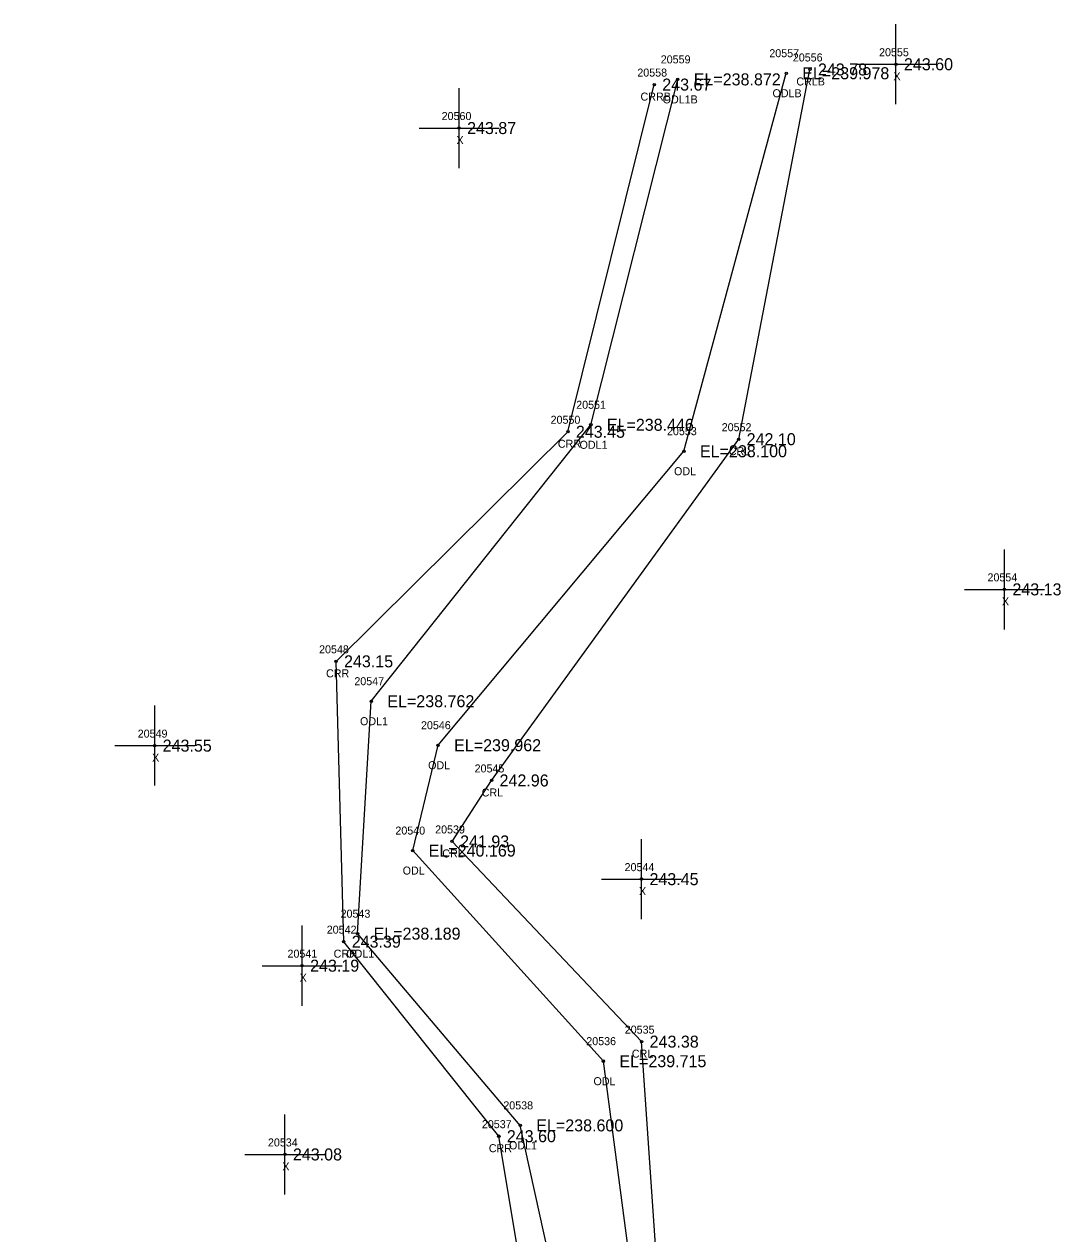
# Model space of a CAD drawing. Extents: x 2275563 to 2277161, y 1075719 to 1076412.
# Drawn here: x 2276399.9 to 2276529.5, y 1076261.3 to 1076412.4 of the extents above; entities that cross this region are included whole.
import ezdxf

# ---------------------------------------------------------------- set-up
doc = ezdxf.new("R2010")
doc.units = 0
for name, color, linetype in [('RD_EX_H2O', 7, 'Continuous'), ('RD_EX_H2O_txCode', 7, 'Continuous'), ('RD_EX_Misc', 7, 'Continuous'), ('RD_EX_Misc_txCode', 7, 'Continuous'), ('RD_EX_TX_H2O_ELEV', 7, 'Continuous'), ('RD_EX_TX_Misc_ELEV', 7, 'Continuous'), ('RD_SMD_Locator', 7, 'Continuous')]:
    doc.layers.add(name, color=color, linetype=linetype)

msp = doc.modelspace()

# ---------------------------------------------------------------- linework, layer by layer
at = {"layer": 'RD_EX_H2O'}
for points in [[(2276371.99, 1076084.86), (2276359.12, 1076090.36), (2276349.87, 1076095.47), (2276335.93, 1076128.95), (2276310.08, 1076180.39), (2276310.66, 1076200.13), (2276321.83, 1076198.34), (2276333.62, 1076185.76), (2276354.83, 1076182.14), (2276364.71, 1076198.02), (2276372.09, 1076234.22), (2276380.37, 1076246.34), (2276391.97, 1076247.22), (2276452.13, 1076223.15), (2276471.36, 1076222.63), (2276478.94, 1076232.98), (2276472.33, 1076282.9), (2276448.49, 1076309.21), (2276451.67, 1076322.37), (2276482.4, 1076359.1), (2276495.19, 1076406.32)], [(2276374.66, 1076053.77), (2276377.62, 1076058.48), (2276375.93, 1076085.62), (2276365.46, 1076098.25), (2276358.16, 1076095.88), (2276352.82, 1076100.61), (2276340.06, 1076130.39), (2276314.72, 1076182.94), (2276314.31, 1076195.95), (2276321.34, 1076195.98), (2276333.33, 1076184.02), (2276355.21, 1076176.64), (2276375.26, 1076196.07), (2276380, 1076232.36), (2276383.62, 1076239.24), (2276390.64, 1076244.46), (2276451.84, 1076220.12), (2276472.79, 1076219.91), (2276480.77, 1076232.08), (2276477.11, 1076285.34), (2276453.42, 1076310.35), (2276458.35, 1076317.97), (2276489.24, 1076360.6), (2276498.15, 1076406.79)], [(2276337.52, 1076082.32), (2276338.14, 1076090.91), (2276325.39, 1076121.38), (2276301.23, 1076176.38), (2276301.47, 1076212.03), (2276303.94, 1076212.33), (2276322.96, 1076208.7), (2276333.72, 1076197.42), (2276353.59, 1076194.54), (2276358.22, 1076208.33), (2276360.94, 1076233.4), (2276370.36, 1076250.64), (2276386.18, 1076258.85), (2276454.86, 1076231.51), (2276469.16, 1076242), (2276461.94, 1076274.88), (2276441.6, 1076298.83), (2276443.32, 1076327.87), (2276470.76, 1076362.4), (2276481.62, 1076405.55)], [(2276306.58, 1076220.1), (2276325.39, 1076214.04), (2276335.43, 1076205.2), (2276348.24, 1076201.78), (2276353.6, 1076208.85), (2276358.58, 1076232.7), (2276367.82, 1076252.56), (2276386.4, 1076261.78), (2276453.31, 1076239.6), (2276463.95, 1076245.24), (2276459.26, 1076273.53), (2276439.87, 1076297.83), (2276438.91, 1076332.85), (2276467.89, 1076361.53), (2276478.69, 1076404.9)]]:
    msp.add_lwpolyline(points, dxfattribs=at)
at = {"layer": 'RD_EX_Misc'}
for p, q in [((2276508.9, 1076402.44), (2276508.9, 1076412.44)), ((2276503.9, 1076407.44), (2276513.9, 1076407.44)), ((2276454.29, 1076394.47), (2276454.29, 1076404.47)), ((2276449.29, 1076399.47), (2276459.29, 1076399.47)), ((2276522.46, 1076336.84), (2276522.46, 1076346.84)), ((2276517.46, 1076341.84), (2276527.46, 1076341.84)), ((2276416.24, 1076317.32), (2276416.24, 1076327.32)), ((2276411.24, 1076322.32), (2276421.24, 1076322.32)), ((2276477.09, 1076300.64), (2276477.09, 1076310.64)), ((2276472.09, 1076305.64), (2276482.09, 1076305.64)), ((2276434.67, 1076289.83), (2276434.67, 1076299.83)), ((2276429.67, 1076294.83), (2276439.67, 1076294.83)), ((2276432.52, 1076266.25), (2276432.52, 1076276.25)), ((2276427.52, 1076271.25), (2276437.52, 1076271.25))]:
    msp.add_line(p, q, dxfattribs=at)
at = {"layer": 'RD_SMD_Locator'}
for centre in [(2276508.9, 1076407.44), (2276495.19, 1076406.32), (2276498.15, 1076406.79), (2276478.69, 1076404.9), (2276481.62, 1076405.55), (2276454.29, 1076399.47), (2276470.76, 1076362.4), (2276467.89, 1076361.53), (2276489.24, 1076360.6), (2276482.4, 1076359.1), (2276522.46, 1076341.84), (2276438.91, 1076332.85), (2276443.32, 1076327.87), (2276416.24, 1076322.32), (2276451.67, 1076322.37), (2276458.35, 1076317.97), (2276448.49, 1076309.21), (2276453.42, 1076310.35), (2276477.09, 1076305.64), (2276441.6, 1076298.83), (2276439.87, 1076297.83), (2276434.67, 1076294.83), (2276477.11, 1076285.34), (2276472.33, 1076282.9), (2276461.94, 1076274.88), (2276459.26, 1076273.53), (2276432.52, 1076271.25)]:
    msp.add_circle(centre, 0.15, dxfattribs=at)

# ---------------------------------------------------------------- texts
at = {"layer": 'RD_EX_H2O_txCode'}
for s, p in [('20557', (2276493.07, 1076408.32)), ('20559', (2276479.5, 1076407.55)), ('20556', (2276496.01, 1076407.79)), ('20558', (2276476.57, 1076405.9)), ('CRLB', (2276496.45, 1076404.79)), ('ODLB', (2276493.47, 1076403.32)), ('CRRB', (2276476.97, 1076402.9)), ('ODL1B', (2276479.74, 1076402.55)), ('20551', (2276468.93, 1076364.4)), ('20550', (2276465.73, 1076362.53)), ('20553', (2276480.28, 1076361.1)), ('20552', (2276487.12, 1076361.6)), ('CRR', (2276466.64, 1076359.53)), ('ODL1', (2276469.35, 1076359.4)), ('CRL', (2276488.01, 1076358.6)), ('ODL', (2276481.16, 1076356.1)), ('20548', (2276436.79, 1076333.85)), ('CRR', (2276437.66, 1076330.85)), ('20547', (2276441.2, 1076329.87)), ('ODL1', (2276441.91, 1076324.87)), ('20546', (2276449.53, 1076324.37)), ('ODL', (2276450.42, 1076319.37)), ('20545', (2276456.23, 1076318.97)), ('CRL', (2276457.12, 1076315.97)), ('20540', (2276446.33, 1076311.21)), ('20539', (2276451.3, 1076311.35)), ('CRL', (2276452.19, 1076308.35)), ('ODL', (2276447.24, 1076306.21)), ('20543', (2276439.48, 1076300.83)), ('20542', (2276437.75, 1076298.83)), ('CRR', (2276438.61, 1076295.83)), ('ODL1', (2276440.19, 1076295.83)), ('20535', (2276475, 1076286.34)), ('20536', (2276470.19, 1076284.9)), ('CRL', (2276475.89, 1076283.34)), ('ODL', (2276471.09, 1076279.9)), ('20538', (2276459.82, 1076276.88)), ('20537', (2276457.14, 1076274.53)), ('ODL1', (2276460.53, 1076271.88)), ('CRR', (2276458.01, 1076271.53))]:
    msp.add_text(s, height=1, dxfattribs=at).set_placement(p)
at = {"layer": 'RD_EX_Misc_txCode'}
for s, p in [('20555', (2276506.79, 1076408.44)), ('X', (2276508.59, 1076405.44)), ('20560', (2276452.11, 1076400.47)), ('X', (2276453.97, 1076397.47)), ('20554', (2276520.34, 1076342.84)), ('X', (2276522.15, 1076339.84)), ('20549', (2276414.12, 1076323.32)), ('X', (2276415.92, 1076320.32)), ('20544', (2276474.98, 1076306.64)), ('X', (2276476.78, 1076303.64)), ('20541', (2276432.84, 1076295.83)), ('X', (2276434.36, 1076292.83)), ('20534', (2276430.4, 1076272.25)), ('X', (2276432.2, 1076269.25))]:
    msp.add_text(s, height=1, dxfattribs=at).set_placement(p)
at = {"layer": 'RD_EX_TX_H2O_ELEV'}
for s, p in [('243.78', (2276499.15, 1076406.04)), ('EL=238.872', (2276483.62, 1076404.8)), ('EL=239.978', (2276497.19, 1076405.57)), ('243.67', (2276479.69, 1076404.15)), ('243.45', (2276468.89, 1076360.78)), ('EL=238.446', (2276472.76, 1076361.65)), ('242.10', (2276490.24, 1076359.85)), ('EL=238.100', (2276484.4, 1076358.35)), ('243.15', (2276439.91, 1076332.1)), ('EL=238.762', (2276445.32, 1076327.12)), ('EL=239.962', (2276453.67, 1076321.62)), ('242.96', (2276459.35, 1076317.22)), ('241.93', (2276454.42, 1076309.6)), ('EL=240.169', (2276450.49, 1076308.46)), ('243.39', (2276440.87, 1076297.08)), ('EL=238.189', (2276443.6, 1076298.08)), ('243.38', (2276478.11, 1076284.59)), ('EL=239.715', (2276474.33, 1076282.15)), ('EL=238.600', (2276463.94, 1076274.13)), ('243.60', (2276460.26, 1076272.78))]:
    msp.add_text(s, height=1.5, dxfattribs=at).set_placement(p)
at = {"layer": 'RD_EX_TX_Misc_ELEV'}
for s, p in [('243.60', (2276509.9, 1076406.69)), ('243.87', (2276455.29, 1076398.72)), ('243.13', (2276523.46, 1076341.09)), ('243.55', (2276417.24, 1076321.57)), ('243.45', (2276478.09, 1076304.89)), ('243.19', (2276435.67, 1076294.08)), ('243.08', (2276433.52, 1076270.5))]:
    msp.add_text(s, height=1.5, dxfattribs=at).set_placement(p)

doc.saveas('drawing.dxf')
